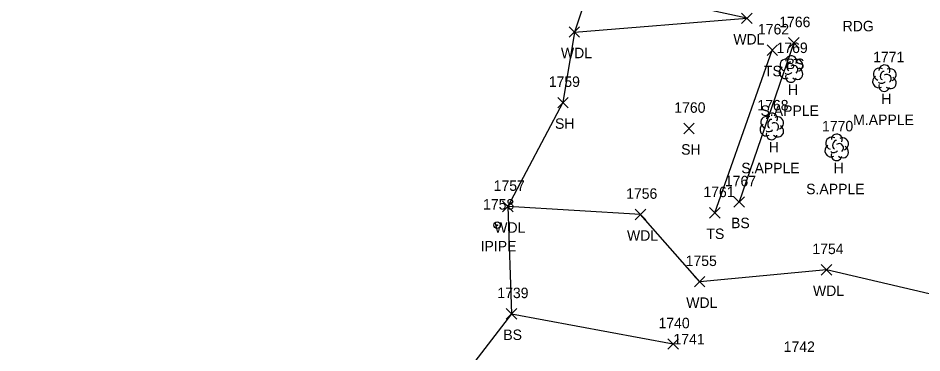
# Model space of a CAD drawing. Extents: x 1633660 to 1636532, y 388643 to 392631.
# Drawn here: x 1634224 to 1634396.6, y 389049.6 to 389113.6 of the extents above; entities that cross this region are included whole.
import ezdxf

# ---------------------------------------------------------------- set-up
doc = ezdxf.new("R2010")
doc.units = 0
for name, color, linetype in [('L_A', 7, 'Continuous'), ('L_C', 7, 'Continuous'), ('L_I', 7, 'Continuous'), ('L_TIC', 7, 'Continuous'), ('LAWA', 7, 'Continuous'), ('LELB', 7, 'Continuous'), ('LSOGP', 7, 'Continuous'), ('LTD', 7, 'Continuous'), ('M_A', 7, 'Continuous'), ('M_I', 7, 'Continuous'), ('MPIP', 7, 'Continuous'), ('P_A', 7, 'Continuous')]:
    doc.layers.add(name, color=color, linetype=linetype)

msp = doc.modelspace()

# ---------------------------------------------------------------- linework, layer by layer
at = {"layer": 'L_TIC'}
for points in [[(1634362.2, 389112.54), (1634364.2, 389114.54)], [(1634364.2, 389112.54), (1634362.2, 389114.54)], [(1634329.26, 389109.92), (1634331.26, 389111.92)], [(1634331.26, 389109.92), (1634329.26, 389111.92)], [(1634371.18, 389107.85), (1634373.18, 389109.85)], [(1634373.18, 389107.85), (1634371.18, 389109.85)], [(1634367.06, 389106.47), (1634369.06, 389108.47)], [(1634369.06, 389106.47), (1634367.06, 389108.47)], [(1634327.06, 389096.44), (1634329.06, 389098.44)], [(1634329.06, 389096.44), (1634327.06, 389098.44)], [(1634351.16, 389091.5), (1634353.16, 389093.5)], [(1634353.16, 389091.5), (1634351.16, 389093.5)], [(1634316.53, 389076.59), (1634318.53, 389078.59)], [(1634318.53, 389076.59), (1634316.53, 389078.59)], [(1634360.74, 389077.46), (1634362.74, 389079.46)], [(1634362.74, 389077.46), (1634360.74, 389079.46)], [(1634341.89, 389075.07), (1634343.89, 389077.07)], [(1634343.89, 389075.07), (1634341.89, 389077.07)], [(1634356.08, 389075.39), (1634358.08, 389077.39)], [(1634358.08, 389075.39), (1634356.08, 389077.39)], [(1634377.42, 389064.51), (1634379.42, 389066.51)], [(1634379.42, 389064.51), (1634377.42, 389066.51)], [(1634353.2, 389062.23), (1634355.2, 389064.23)], [(1634355.2, 389062.23), (1634353.2, 389064.23)], [(1634317.24, 389056.1), (1634319.24, 389058.1)], [(1634319.24, 389056.1), (1634317.24, 389058.1)], [(1634348.11, 389050.34), (1634350.11, 389052.34)], [(1634350.11, 389050.34), (1634348.11, 389052.34)]]:
    msp.add_lwpolyline(points, dxfattribs=at)
at = {"layer": 'LAWA'}
for points in [[(1634330.26, 389110.92), (1634363.2, 389113.54), (1634333.3, 389120.05)], [(1634443.98, 389012.05), (1634437.85, 389030.5), (1634426.41, 389046.1), (1634414.67, 389057.02), (1634378.42, 389065.51), (1634354.2, 389063.23), (1634342.89, 389076.07), (1634317.53, 389077.59)]]:
    msp.add_lwpolyline(points, dxfattribs=at)
at = {"layer": 'LELB'}
for points in [[(1634357.08, 389076.39), (1634368.06, 389107.47)], [(1634372.18, 389108.85), (1634361.74, 389078.46)], [(1634318.24, 389057.1), (1634349.11, 389051.34)]]:
    msp.add_lwpolyline(points, dxfattribs=at)
at = {"layer": 'LSOGP'}
msp.add_lwpolyline([(1634333.3, 389120.05), (1634330.26, 389110.92), (1634328.06, 389097.44), (1634317.53, 389077.59), (1634318.24, 389057.1), (1634304.06, 389038.64), (1634293.32, 389038.19), (1634275.87, 389031.31), (1634254.18, 389019.53), (1634228.12, 389003.28), (1634202.79, 388974.39)], dxfattribs=at)
at = {"layer": 'LTD'}
for p, q in [((1634371.62, 389103.91), (1634371.62, 389103.91)), ((1634371.62, 389103.91), (1634371.62, 389103.91)), ((1634389.45, 389102.16), (1634389.45, 389102.16)), ((1634389.45, 389102.16), (1634389.45, 389102.16)), ((1634367.95, 389092.95), (1634367.95, 389092.95)), ((1634367.95, 389092.95), (1634367.95, 389092.95)), ((1634380.34, 389088.95), (1634380.34, 389088.95)), ((1634380.34, 389088.95), (1634380.34, 389088.95))]:
    msp.add_line(p, q, dxfattribs=at)
for centre in [(1634371.67, 389105.35), (1634389.49, 389103.59), (1634368, 389094.39), (1634380.39, 389090.39)]:
    msp.add_arc(centre, 1.05, 335.5272, 180.9563, dxfattribs=at)
for centre, major_axis, ratio, start_param, end_param in [((1634370.83, 389104.58), (1.21, -0.51), 0.895232, 1.570796, 4.712389), ((1634372.66, 389104.5), (-1.14, -0.48), 0.949671, 1.570796, 4.712389), ((1634370.54, 389103.2), (0.58, -1.04), 0.959034, 3.141593, 6.283185), ((1634371.41, 389104.37), (-0.208, -0.792), 0.645439, 3.141593, 6.283185), ((1634372.12, 389103.74), (-0.5, 0.667), 0.989748, 3.141593, 6.283185), ((1634372.62, 389103.08), (-1.09, 0.79), 0.841452, 1.570796, 4.712389), ((1634388.65, 389102.83), (1.21, -0.51), 0.895232, 1.570796, 4.712389), ((1634390.49, 389102.74), (-1.14, -0.48), 0.949671, 1.570796, 4.712389), ((1634371.62, 389102.41), (0.26, 1.06), 0.942809, 1.570796, 4.712389), ((1634371.16, 389103.16), (-0.625, -0.083), 0.423636, 0, 3.141593), ((1634388.36, 389101.45), (0.58, -1.04), 0.959034, 3.141593, 6.283185), ((1634389.24, 389102.62), (-0.208, -0.792), 0.645439, 3.141593, 6.283185), ((1634389.95, 389101.99), (-0.5, 0.667), 0.989748, 3.141593, 6.283185), ((1634390.45, 389101.33), (-1.09, 0.79), 0.841452, 1.570796, 4.712389), ((1634389.45, 389100.66), (0.26, 1.06), 0.942809, 1.570796, 4.712389), ((1634388.99, 389101.41), (-0.625, -0.083), 0.423636, 0, 3.141593), ((1634367.16, 389093.62), (1.21, -0.51), 0.895232, 1.570796, 4.712389), ((1634367.74, 389093.41), (-0.208, -0.792), 0.645439, 3.141593, 6.283185), ((1634368.45, 389092.79), (-0.5, 0.667), 0.989748, 3.141593, 6.283185), ((1634368.99, 389093.54), (-1.14, -0.48), 0.949671, 1.570796, 4.712389), ((1634366.87, 389092.25), (0.58, -1.04), 0.959034, 3.141593, 6.283185), ((1634367.49, 389092.2), (-0.625, -0.083), 0.423636, 0, 3.141593), ((1634368.95, 389092.12), (-1.09, 0.79), 0.841452, 1.570796, 4.712389), ((1634367.95, 389091.45), (0.26, 1.06), 0.942809, 1.570796, 4.712389), ((1634379.55, 389089.62), (1.21, -0.51), 0.895232, 1.570796, 4.712389), ((1634380.14, 389089.41), (-0.208, -0.792), 0.645439, 3.141593, 6.283185), ((1634381.39, 389089.53), (-1.14, -0.48), 0.949671, 1.570796, 4.712389), ((1634379.26, 389088.24), (0.58, -1.04), 0.959034, 3.141593, 6.283185), ((1634380.84, 389088.78), (-0.5, 0.667), 0.989748, 3.141593, 6.283185), ((1634381.34, 389088.12), (-1.09, 0.79), 0.841452, 1.570796, 4.712389), ((1634380.34, 389087.45), (0.26, 1.06), 0.942809, 1.570796, 4.712389), ((1634379.89, 389088.2), (-0.625, -0.083), 0.423636, 0, 3.141593)]:
    msp.add_ellipse(centre, major_axis=major_axis, ratio=ratio, start_param=start_param, end_param=end_param, dxfattribs=at)
at = {"layer": 'MPIP'}
for radius in [0.625, 0.0833]:
    msp.add_circle((1634315.5, 389074.02), radius, dxfattribs=at)

# ---------------------------------------------------------------- texts
at = {"layer": 'L_A'}
for s, p in [('WDL', (1634360.62, 389108.54)), ('WDL', (1634327.68, 389105.92)), ('BS', (1634370.63, 389103.85)), ('TS', (1634366.46, 389102.47)), ('H', (1634371.05, 389098.91)), ('H', (1634388.88, 389097.16)), ('SH', (1634326.55, 389092.44)), ('SH', (1634350.65, 389087.5)), ('H', (1634367.38, 389087.95)), ('H', (1634379.78, 389083.95)), ('WDL', (1634314.95, 389072.59)), ('BS', (1634360.18, 389073.46)), ('WDL', (1634340.3, 389071.07)), ('TS', (1634355.48, 389071.39)), ('WDL', (1634375.83, 389060.51)), ('WDL', (1634351.62, 389058.23)), ('BS', (1634316.68, 389052.1))]:
    msp.add_text(s, height=2, dxfattribs=at).set_placement(p)
at = {"layer": 'L_C'}
for s, p in [('S.APPLE', (1634365.81, 389094.91)), ('M.APPLE', (1634383.51, 389093.16)), ('S.APPLE', (1634362.14, 389083.95)), ('S.APPLE', (1634374.53, 389079.95))]:
    msp.add_text(s, height=2, dxfattribs=at).set_placement(p)
at = {"layer": 'L_I'}
for s, p in [('1766', (1634369.39, 389111.85)), ('1762', (1634365.32, 389110.47)), ('1769', (1634368.87, 389106.91)), ('1771', (1634387.32, 389105.16)), ('1759', (1634325.36, 389100.44)), ('1760', (1634349.34, 389095.5)), ('1768', (1634365.21, 389095.95)), ('1770', (1634377.56, 389091.95)), ('1767', (1634359, 389081.46)), ('1757', (1634314.84, 389080.59)), ('1756', (1634340.14, 389079.07)), ('1761', (1634354.9, 389079.39)), ('1754', (1634375.72, 389068.51)), ('1755', (1634351.51, 389066.23)), ('1739', (1634315.54, 389060.1)), ('1740', (1634346.33, 389054.34)), ('1741', (1634349.18, 389051.27)), ('1742', (1634370.24, 389049.82))]:
    msp.add_text(s, height=2, dxfattribs=at).set_placement(p)
at = {"layer": 'M_A'}
msp.add_text('IPIPE', height=2, dxfattribs=at).set_placement((1634312.34, 389069.02))
at = {"layer": 'M_I'}
msp.add_text('1758', height=2, dxfattribs=at).set_placement((1634312.81, 389077.02))
at = {"layer": 'P_A'}
msp.add_text('RDG', height=2, dxfattribs=at).set_placement((1634381.5, 389111.06))

doc.saveas('drawing.dxf')
